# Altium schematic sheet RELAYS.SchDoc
size A
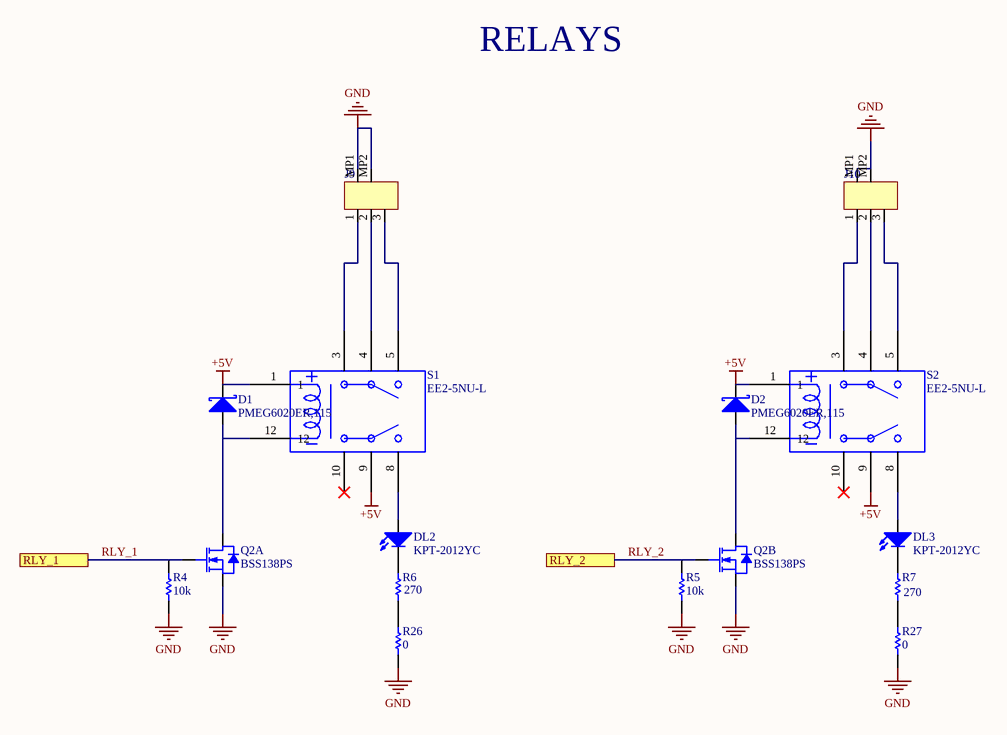
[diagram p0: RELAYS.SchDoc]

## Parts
D1  PMEG6020ER,115  [SOD123]
D2  PMEG6020ER,115  [SOD123]
DL2  KPT-2012YC  [CHIPLED_0805]
DL3  KPT-2012YC  [CHIPLED_0805]
J9  1771033  [1771033-Footprint-1]  (value not drawn)
J10  1771033  [1771033-Footprint-1]  (value not drawn)
Q2  BSS138PS  [SOT363]  (parts A,B of 2)
R4  value 10k  [RES-0402]  (hidden comment: CRCW040210K0JNED)
R5  value 10k  [RES-0402]  (hidden comment: CRCW040210K0JNED)
R6  value 270  [RES-0402]  (hidden comment: RC0402JR-07270RL)
R7  value 270  [RES-0402]  (hidden comment: RC0402JR-07270RL)
R26  value 0  [RES-0402]  (hidden comment: CRCW04020000Z0EDC)
R27  value 0  [RES-0402]  (hidden comment: CRCW04020000Z0EDC)
S1  EE2-5NU-L  [EE2-5NU-L-Footprint-1]
S2  EE2-5NU-L  [EE2-5NU-L-Footprint-1]

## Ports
RLY_1, RLY_2

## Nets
+5V: D1.C D2.C S1.1 S1.9 S2.1 S2.9
GND: J9.MP1 J9.MP2 J10.MP1 J10.MP2 Q2.1(S) Q2.4(S) R4.2 R5.2 R26.1 R27.1
RLY_1: Q2.2(G) R4.1 ; port RLY_1
RLY_2: Q2.5(G) R5.1 ; port RLY_2
NetD1_A: D1.A Q2.6(D) S1.12
NetD2_A: D2.A Q2.3(D) S2.12
NetDL2_A: DL2.A S1.8
NetDL2_C: DL2.C R6.2
NetDL3_A: DL3.A S2.8
NetDL3_C: DL3.C R7.2
NetJ9_1: J9.1 S1.3
NetJ9_2: J9.2 S1.4
NetJ9_3: J9.3 S1.5
NetJ10_1: J10.1 S2.3
NetJ10_2: J10.2 S2.4
NetJ10_3: J10.3 S2.5
NetR6_1: R6.1 R26.2
NetR7_1: R7.1 R27.2

Not connected (* = marked no-connect by the designer): S1 10*; S2 10*

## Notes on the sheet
- RELAYS

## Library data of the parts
D1 D2 = D0035-A.2: DIODE SCHOTTKY SMD 2A 60V SOD123; Manufacturer: Nexperia; Code Arduino: 2208
DL2 DL3 = L0001-A.2: LED SMD 0805 YELLOW CLEAR; Manufacturer: Kingbright; Code Arduino: 0044
J9 J10 = J0110-A.2: CONN TERM BLK 3POS R/A 2.5MM SMD; Manufacturer: Phoenix Contact; Current Rating: 6A; Wire Gauge (Min): 24AWG; Number of Positions: 3; Code Arduino: J0110; Wire Gauge (Max): 26AWG; Voltage Rating: 160V; Current: 5A; Number of Levels: 1; Voltage: 150V
Q2 = T0012-A.3: MOSFET N-CH 2x 60V 0.32A SOT363; Manufacturer: Nexperia; Code Arduino: 2323; Device Type: Mosfet 2N-CH SMD
R4 R5 = R0004-A.3: RES CHIP 0402 10K 5% 1/16W; Manufacturer: Vishay; Code Arduino: 0136; Power: 63mW
R6 R7 = R0016-A.3: RES CHIP 0402 270R 5% 1/16W; Manufacturer: Yageo; Power: 63mW; Code Arduino: 2228
R26 R27 = R0000-A.3: RES CHIP 0402 0R 1/16W; Manufacturer: Vishay; Code Arduino: 0039; Power: 63mW; Tolerance: J
S1 S2 = S0009-A.4: RELAY GEN PURPOSE DPDT 2A 250V; Manufacturer: KEMET; Max Voltage Rating (DC): 220V; Number of Poles: 1; Release Time: 1ms; Power Consumption: 140mW; Coil Resistance: 178R; Coil Current: 28mA; Code Arduino: S0009; Coil Type: Non-Latching; Coil Voltage (DC): 5V; Relay Type: General Purpose; Operate Time: 2ms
